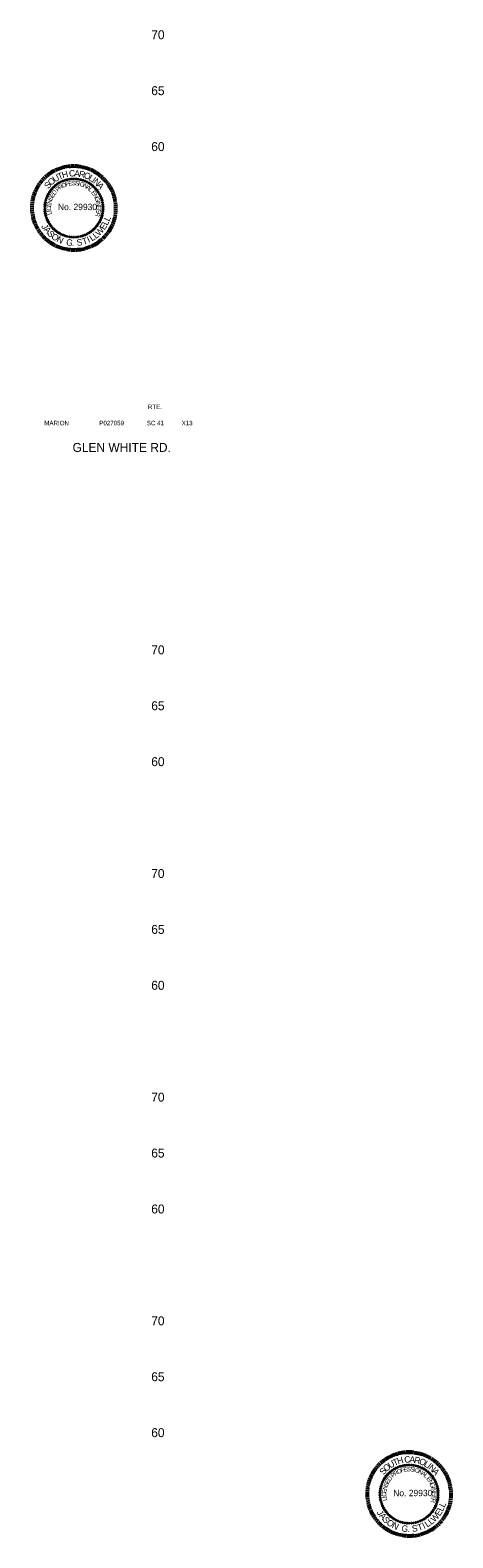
# Model space of a CAD drawing. Extents: x 1001 to 1184, y 1001 to 1562.
# Drawn here: x 1146.1 to 1183.9, y 1001 to 1135.8 of the extents above; entities that cross this region are included whole.
import ezdxf

# ---------------------------------------------------------------- set-up
doc = ezdxf.new("R2010")
doc.units = 0
for name, color, linetype in [('RD_HC_Cl', 7, 'Continuous'), ('RD_SHT_TX', 7, 'Continuous'), ('RD_TX_PEShield', 7, 'Continuous'), ('RD_XS_TX_Elev_EX', 7, 'Continuous')]:
    doc.layers.add(name, color=color, linetype=linetype)

# ---------------------------------------------------------------- blocks, each defined once
blk = doc.blocks.new('STILLWELL')
at = {"layer": 'RD_TX_PEShield'}
for p, q in [((-25.1, 24.7), (-27.4, 27.1)), ((-23.8, 25.9), (-26, 28.4)), ((-22.5, 27), (-24.5, 29.6)), ((-21.1, 28.1), (-23, 30.7)), ((-19.7, 29.1), (-21.5, 31.8)), ((-18.2, 30), (-19.9, 32.8)), ((-16.7, 30.8), (-18.2, 33.7)), ((-15.1, 31.6), (-16.5, 34.6)), ((-13.6, 32.3), (-14.8, 35.3)), ((-11.9, 32.9), (-13, 36)), ((-10.3, 33.4), (-11.2, 36.6)), ((-8.6, 33.9), (-9.4, 37.1)), ((-6.9, 34.3), (-7.5, 37.5)), ((-5.2, 34.6), (-5.7, 37.8)), ((-3.5, 34.8), (-3.8, 38)), ((-1.8, 34.9), (-1.9, 38.2)), ((0, 34.9), (0, 38.2)), ((1.7, 34.9), (1.9, 38.2)), ((3.4, 34.8), (3.7, 38)), ((5.2, 34.6), (5.6, 37.8)), ((6.9, 34.3), (7.5, 37.5)), ((8.6, 33.9), (9.3, 37.1)), ((10.2, 33.4), (11.2, 36.6)), ((11.9, 32.9), (13, 36)), ((13.5, 32.3), (14.7, 35.3)), ((15.1, 31.6), (16.5, 34.6)), ((16.6, 30.8), (18.2, 33.7)), ((18.2, 30), (19.8, 32.8)), ((19.6, 29.1), (21.4, 31.8)), ((21.1, 28.1), (23, 30.7)), ((22.4, 27), (24.5, 29.6)), ((23.8, 25.9), (25.9, 28.4)), ((25, 24.7), (27.3, 27.1)), ((-32.9, 13.4), (-35.9, 14.7)), ((-32.2, 15), (-35.1, 16.4)), ((-31.4, 16.5), (-34.2, 18.1)), ((-30.5, 18), (-33.3, 19.7)), ((-29.5, 19.4), (-32.2, 21.3)), ((-28.5, 20.9), (-31.1, 22.8)), ((-27.4, 22.2), (-29.9, 24.3)), ((-26.3, 23.5), (-28.7, 25.7)), ((26.2, 23.5), (28.6, 25.7)), ((27.4, 22.2), (29.9, 24.3)), ((28.5, 20.9), (31.1, 22.8)), ((29.5, 19.4), (32.2, 21.3)), ((30.4, 18), (33.2, 19.7)), ((31.3, 16.5), (34.2, 18.1)), ((32.1, 15), (35.1, 16.4)), ((32.9, 13.4), (35.9, 14.7)), ((-35.9, -0.1), (-39.2, 0)), ((-35.8, 1.7), (-39.1, 1.9)), ((-35.6, 3.4), (-38.9, 3.8)), ((-35.4, 5.1), (-38.6, 5.7)), ((-35.1, 6.8), (-38.2, 7.5)), ((-34.6, 8.5), (-37.8, 9.4)), ((-34.1, 10.2), (-37.2, 11.2)), ((-33.6, 11.8), (-36.6, 12.9)), ((33.5, 11.8), (36.6, 12.9)), ((34.1, 10.2), (37.2, 11.2)), ((34.6, 8.5), (37.7, 9.4)), ((35, 6.8), (38.2, 7.5)), ((35.3, 5.1), (38.5, 5.7)), ((35.6, 3.4), (38.8, 3.8)), ((35.7, 1.7), (39, 1.9)), ((35.8, -0.1), (39.1, 0)), ((-35.9, -1.8), (-39.2, -1.9)), ((-35.8, -3.5), (-39.1, -3.8)), ((-35.6, -5.3), (-38.9, -5.6)), ((-35.4, -7), (-38.6, -7.5)), ((-35.1, -8.7), (-38.2, -9.4)), ((-34.6, -10.4), (-37.8, -11.2)), ((-34.1, -12), (-37.2, -13)), ((34.1, -12), (37.2, -13)), ((34.6, -10.4), (37.7, -11.2)), ((35, -8.7), (38.2, -9.4)), ((35.3, -7), (38.5, -7.5)), ((35.6, -5.3), (38.8, -5.6)), ((35.7, -3.5), (39, -3.8)), ((35.8, -1.8), (39.1, -1.9)), ((-33.6, -13.6), (-36.6, -14.8)), ((-32.9, -15.3), (-35.9, -16.6)), ((-32.2, -16.8), (-35.1, -18.3)), ((-31.4, -18.4), (-34.2, -19.9)), ((-30.5, -19.9), (-33.3, -21.6)), ((-29.5, -21.3), (-32.2, -23.2)), ((-28.5, -22.7), (-31.1, -24.7)), ((-27.4, -24.1), (-29.9, -26.2)), ((-26.3, -25.4), (-28.7, -27.6)), ((-25.1, -26.6), (-27.4, -28.9)), ((25, -26.6), (27.3, -28.9)), ((26.2, -25.4), (28.6, -27.6)), ((27.4, -24.1), (29.9, -26.2)), ((28.5, -22.7), (31.1, -24.7)), ((29.5, -21.3), (32.2, -23.2)), ((30.4, -19.9), (33.2, -21.6)), ((31.3, -18.4), (34.2, -19.9)), ((32.1, -16.8), (35.1, -18.3)), ((32.9, -15.3), (35.9, -16.6)), ((33.5, -13.6), (36.6, -14.8)), ((-23.8, -27.8), (-26, -30.2)), ((-22.5, -28.9), (-24.5, -31.4)), ((-21.1, -29.9), (-23, -32.6)), ((-19.7, -30.9), (-21.5, -33.7)), ((-18.2, -31.8), (-19.9, -34.7)), ((-16.7, -32.7), (-18.2, -35.6)), ((-15.1, -33.5), (-16.5, -36.4)), ((-13.6, -34.1), (-14.8, -37.2)), ((-11.9, -34.8), (-13, -37.8)), ((-10.3, -35.3), (-11.2, -38.4)), ((-8.6, -35.8), (-9.4, -38.9)), ((-6.9, -36.1), (-7.5, -39.3)), ((-5.2, -36.4), (-5.7, -39.7)), ((-3.5, -36.6), (-3.8, -39.9)), ((-1.8, -36.8), (-1.9, -40)), ((0, -36.8), (0, -40.1)), ((1.7, -36.8), (1.9, -40)), ((3.4, -36.6), (3.7, -39.9)), ((5.2, -36.4), (5.6, -39.7)), ((6.9, -36.1), (7.5, -39.3)), ((8.6, -35.8), (9.3, -38.9)), ((10.2, -35.3), (11.2, -38.4)), ((11.9, -34.8), (13, -37.8)), ((13.5, -34.1), (14.7, -37.2)), ((15.1, -33.5), (16.5, -36.4)), ((16.6, -32.7), (18.2, -35.6)), ((18.2, -31.8), (19.8, -34.7)), ((19.6, -30.9), (21.4, -33.7)), ((21.1, -29.9), (23, -32.6)), ((22.4, -28.9), (24.5, -31.4)), ((23.8, -27.8), (25.9, -30.2))]:
    blk.add_line(p, q, dxfattribs=at)
for centre in [(-21.9, 13.2), (-20.7, 14.9), (-19.5, 16.4), (-18.1, 17.8), (-16.6, 19.2), (-15, 20.4), (-13.3, 21.5), (-11.6, 22.4), (-9.8, 23.2), (-7.9, 23.9), (-6, 24.4), (-4, 24.8), (-2, 25), (0, 25.1), (2, 25), (3.9, 24.8), (5.9, 24.4), (7.8, 23.9), (9.7, 23.2), (11.5, 22.4), (13.3, 21.5), (15, 20.4), (16.5, 19.2), (18, 17.8), (19.4, 16.4), (20.7, 14.9), (21.8, 13.2), (-26.1, 0.1), (-25.9, 2.1), (-25.6, 4), (-25.1, 6), (-24.5, 7.9), (-23.8, 9.7), (-22.9, 11.5), (22.9, 11.5), (23.7, 9.7), (24.5, 7.9), (25.1, 6), (25.5, 4), (25.8, 2.1), (26, 0.1), (-26.1, -1.9), (-25.9, -3.9), (-25.6, -5.9), (-25.1, -7.8), (-24.5, -9.7), (-23.8, -11.6), (-22.9, -13.4), (22.9, -13.4), (23.7, -11.6), (24.5, -9.7), (25.1, -7.8), (25.5, -5.9), (25.8, -3.9), (26, -1.9), (-21.9, -15.1), (-20.7, -16.7), (-19.5, -18.3), (-18.1, -19.7), (-16.6, -21), (-15, -22.2), (-13.3, -23.3), (-11.6, -24.3), (-9.8, -25.1), (-7.9, -25.8), (-6, -26.3), (-4, -26.7), (-2, -26.9), (0, -27), (2, -26.9), (3.9, -26.7), (5.9, -26.3), (7.8, -25.8), (9.7, -25.1), (11.5, -24.3), (13.3, -23.3), (15, -22.2), (16.5, -21), (18, -19.7), (19.4, -18.3), (20.7, -16.7), (21.8, -15.1)]:
    blk.add_circle(centre, 0.49, dxfattribs=at)
for s, height, rotation, p in [('U', 5.68, 32.2152, (-16.9, 21.8)), ('T', 5.68, 23.5044, (-13.2, 24.1)), ('H', 5.68, 16.1357, (-9.9, 25.6)), ('C', 5.68, 4.076, (-4.2, 27.1)), ('A', 5.68, 355.3651, (0.1, 27.4)), ('R', 5.68, 347.3188, (4.1, 27.1)), ('O', 5.68, 338.6079, (8.3, 26.2)), ('L', 5.68, 329.226, (12.6, 24.4)), ('S', 5.68, 49.6435, (-22.9, 15.8)), ('O', 5.68, 41.5972, (-20.4, 18.8)), ('D', 3.92, 52.5376, (-17.1, 10.3)), ('P', 3.92, 41.0022, (-14.5, 13.5)), ('R', 3.92, 33.3057, (-12.5, 15.3)), ('O', 3.92, 24.9735, (-10, 16.9)), ('F', 3.92, 15.9995, (-7.1, 18.3)), ('E', 3.92, 8.9511, (-4.7, 19)), ('S', 3.92, 1.2546, (-1.9, 19.4)), ('S', 3.92, 353.558, (0.8, 19.5)), ('I', 3.92, 345.8615, (3.5, 19.2)), ('O', 3.92, 342.6583, (4.7, 19)), ('N', 3.92, 333.6842, (7.7, 18)), ('A', 3.92, 325.3521, (10.4, 16.7)), ('L', 3.92, 317.6555, (12.6, 15.1)), ('E', 3.92, 308.0396, (15.1, 12.8)), ('I', 5.68, 322.5218, (15.5, 22.8)), ('N', 5.68, 319.1729, (16.8, 21.8)), ('A', 5.68, 310.4621, (20.1, 19)), ('C', 3.92, 92.2915, (-20.4, -3.2)), ('E', 3.92, 83.9594, (-20.5, -0.2)), ('N', 3.92, 76.2628, (-20.2, 2.5)), ('S', 3.92, 67.9307, (-19.5, 5.4)), ('E', 3.92, 60.2341, (-18.5, 7.9)), ('N', 3.92, 300.343, (16.8, 10.6)), ('G', 3.92, 292.0109, (18.3, 8.1)), ('I', 3.92, 283.0368, (19.5, 5.1)), ('N', 3.92, 279.8336, (19.8, 4)), ('E', 3.92, 271.5014, (20.3, 1.1)), ('I', 3.92, 95.4947, (-20.2, -4.3)), ('L', 3.92, 101.9075, (-19.7, -6.6)), ('R', 3.92, 256.1083, (20.1, -4.4)), ('E', 3.92, 263.8049, (20.4, -1.7)), ('L', 5.68, 65.098, (30, -16.9)), ('L', 5.68, 65.098, (31.6, -13.3)), ('J', 5.68, 299.033, (-29.4, -17.3)), ('A', 5.68, 310.5887, (-27.2, -20.6)), ('S', 5.68, 310.5887, (-24.3, -24)), ('O', 5.68, 321.0072, (-20.8, -27.4)), ('N', 5.68, 333.4326, (-16, -30.8)), ('I', 5.68, 25.3991, (13.3, -32.2)), ('L', 5.68, 34.0644, (16.2, -30.9)), ('L', 5.68, 37.6708, (19.6, -28.7)), ('W', 5.68, 47.0518, (22.6, -26.4)), ('E', 5.68, 56.4327, (27.3, -21.1)), ('G', 5.68, 352.2045, (-7.2, -34.2)), ('.', 5.68, 0.8698, (-1.8, -34.9)), ('S', 5.68, 8.0826, (2.9, -34.8)), ('T', 5.68, 18.9019, (8.5, -33.9))]:
    blk.add_text(s, height=height, rotation=rotation, dxfattribs=at).set_placement(p)
blk.add_text('No. 29930', height=5.68, dxfattribs=at).set_placement((-14.3, -2.8))

msp = doc.modelspace()

# ---------------------------------------------------------------- block references
at = {"layer": 'RD_HC_Cl', "xscale": 0.1, "yscale": 0.10000000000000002}
for p in [(1150, 1120), (1180, 1005)]:
    msp.add_blockref('STILLWELL', p, dxfattribs=at)

# ---------------------------------------------------------------- texts
at = {"layer": 'RD_SHT_TX'}
for s, height, p in [('RTE.', 0.4, (1156.62, 1101.93)), ('MARION', 0.4, (1147.35, 1100.48)), ('P027059', 0.4, (1152.27, 1100.48)), ('SC 41', 0.4, (1156.52, 1100.48)), ('X13', 0.4, (1159.64, 1100.48)), ('GLEN WHITE RD.', 0.8, (1149.88, 1098.1))]:
    msp.add_text(s, height=height, dxfattribs=at).set_placement(p)
at = {"layer": 'RD_XS_TX_Elev_EX'}
for s, p in [('70', (1156.92, 1135)), ('65', (1156.92, 1130)), ('60', (1156.92, 1125)), ('70', (1156.92, 1080)), ('65', (1156.92, 1075)), ('60', (1156.92, 1070)), ('70', (1156.92, 1060)), ('65', (1156.92, 1055)), ('60', (1156.92, 1050)), ('70', (1156.92, 1040)), ('65', (1156.92, 1035)), ('60', (1156.92, 1030)), ('70', (1156.92, 1020)), ('65', (1156.92, 1015)), ('60', (1156.92, 1010))]:
    msp.add_text(s, height=0.8, dxfattribs=at).set_placement(p)

doc.saveas('drawing.dxf')
